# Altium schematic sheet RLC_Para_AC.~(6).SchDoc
size A4
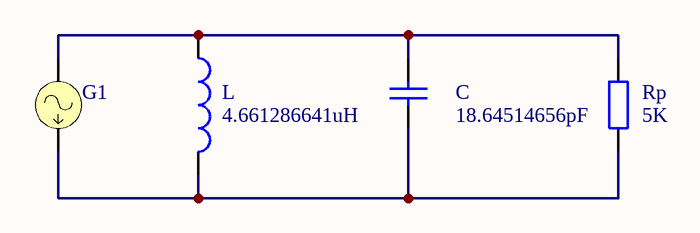
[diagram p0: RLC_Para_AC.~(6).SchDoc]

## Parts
C  value 18.64514656pF  [RAD-0.3]  (hidden comment: Cap)
G1  ISIN  (value not drawn)
L  value 4.661286641uH  [0402-A]  (hidden comment: Inductor)
Rp  value 5K  [AXIAL-0.4]  (hidden comment: Res2)

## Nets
NetC_1: C.1 G1.1 L.1 Rp.2
NetC_2: C.2 G1.2 L.2 Rp.1

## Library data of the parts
C = Cap: Capacitor
G1 = ISIN: Sinusoidal Current Source
L = Inductor: Code_IEC: 1005
Rp = Res2: Resistor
